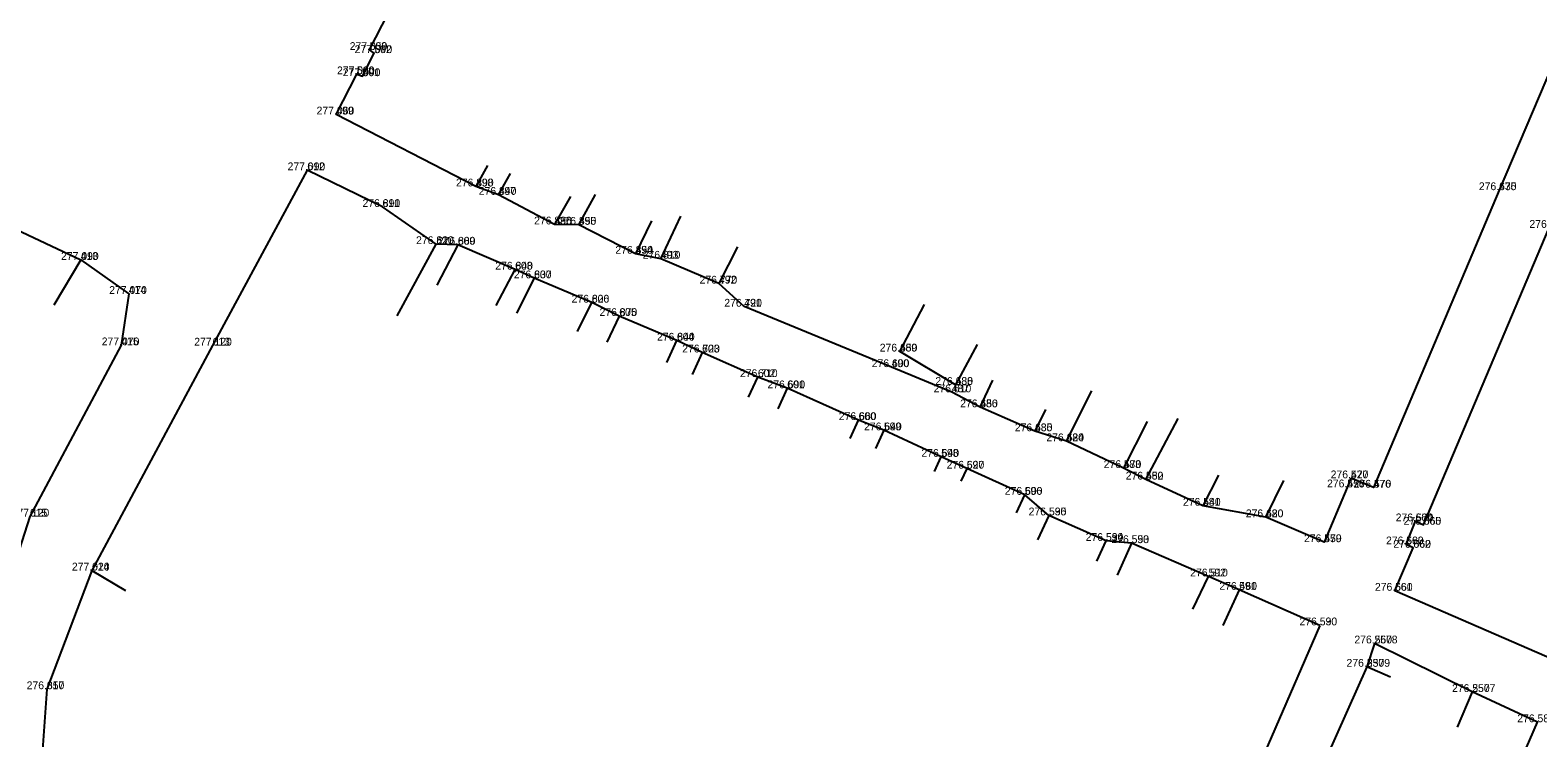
# Model space of a CAD drawing. Extents: x -776701 to -776081, y -974398 to -973771.
# Drawn here: x -776485.83 to -776437.45, y -974103.58 to -974080.86 of the extents above; entities that cross this region are included whole.
import ezdxf

# ---------------------------------------------------------------- set-up
doc = ezdxf.new("R2010")
doc.units = 0
for name, color, linetype in [('1 Body-bod', 7, 'Continuous'), ('11 Rozhrani-nezpev zpev schody', 7, 'Continuous'), ('2 Body-cislo', 7, 'Continuous'), ('3 Body-vyska', 7, 'Continuous'), ('47 Opěrné zdi', 7, 'Continuous'), ('7 Ploty', 7, 'Continuous')]:
    doc.layers.add(name, color=color, linetype=linetype)

msp = doc.modelspace()

# ---------------------------------------------------------------- linework, layer by layer
at = {"layer": '1 Body-bod'}
for p, q in [((-776474.94, -974081.5), (-776474.94, -974081.5)), ((-776474.79, -974081.6), (-776474.79, -974081.6)), ((-776475.35, -974082.28), (-776475.35, -974082.28)), ((-776475.17, -974082.34), (-776475.17, -974082.34)), ((-776476.01, -974083.57), (-776476.01, -974083.57)), ((-776476.94, -974085.36), (-776476.94, -974085.36)), ((-776471.53, -974085.88), (-776471.53, -974085.88)), ((-776470.8, -974086.15), (-776470.8, -974086.15)), ((-776438.7, -974086), (-776438.7, -974086)), ((-776474.53, -974086.54), (-776474.53, -974086.54)), ((-776469.01, -974087.1), (-776469.01, -974087.1)), ((-776468.23, -974087.11), (-776468.23, -974087.11)), ((-776472.8, -974087.73), (-776472.8, -974087.73)), ((-776472.11, -974087.75), (-776472.11, -974087.75)), ((-776466.41, -974088.04), (-776466.41, -974088.04)), ((-776465.59, -974088.2), (-776465.59, -974088.2)), ((-776484.21, -974088.24), (-776484.21, -974088.24)), ((-776470.27, -974088.55), (-776470.27, -974088.55)), ((-776469.66, -974088.83), (-776469.66, -974088.83)), ((-776463.73, -974089), (-776463.73, -974089)), ((-776482.67, -974089.33), (-776482.67, -974089.33)), ((-776467.81, -974089.61), (-776467.81, -974089.61)), ((-776466.93, -974090.04), (-776466.93, -974090.04)), ((-776462.92, -974089.74), (-776462.92, -974089.74)), ((-776482.91, -974090.98), (-776482.91, -974090.98)), ((-776479.98, -974090.99), (-776479.98, -974090.99)), ((-776465.08, -974090.83), (-776465.08, -974090.83)), ((-776464.27, -974091.21), (-776464.27, -974091.21)), ((-776457.93, -974091.18), (-776457.93, -974091.18)), ((-776462.48, -974092), (-776462.48, -974092)), ((-776458.19, -974091.68), (-776458.19, -974091.68)), ((-776461.54, -974092.36), (-776461.54, -974092.36)), ((-776456.26, -974092.49), (-776456.26, -974092.49)), ((-776456.14, -974092.25), (-776456.14, -974092.25)), ((-776455.35, -974092.97), (-776455.35, -974092.97)), ((-776459.25, -974093.38), (-776459.25, -974093.38)), ((-776458.44, -974093.71), (-776458.44, -974093.71)), ((-776453.59, -974093.74), (-776453.59, -974093.74)), ((-776452.58, -974094.06), (-776452.58, -974094.06)), ((-776456.6, -974094.56), (-776456.6, -974094.56)), ((-776455.78, -974094.94), (-776455.78, -974094.94)), ((-776450.75, -974094.92), (-776450.75, -974094.92)), ((-776450.03, -974095.29), (-776450.03, -974095.29)), ((-776443.45, -974095.25), (-776443.45, -974095.25)), ((-776453.92, -974095.78), (-776453.92, -974095.78)), ((-776443.57, -974095.54), (-776443.57, -974095.54)), ((-776442.73, -974095.55), (-776442.73, -974095.55)), ((-776453.14, -974096.44), (-776453.14, -974096.44)), ((-776448.2, -974096.13), (-776448.2, -974096.13)), ((-776446.18, -974096.5), (-776446.18, -974096.5)), ((-776441.38, -974096.63), (-776441.38, -974096.63)), ((-776441.12, -974096.74), (-776441.12, -974096.74)), ((-776451.31, -974097.26), (-776451.31, -974097.26)), ((-776450.49, -974097.33), (-776450.49, -974097.33)), ((-776444.31, -974097.3), (-776444.31, -974097.3)), ((-776441.68, -974097.37), (-776441.68, -974097.37)), ((-776441.45, -974097.48), (-776441.45, -974097.48)), ((-776483.85, -974098.21), (-776483.85, -974098.21)), ((-776448.02, -974098.4), (-776448.02, -974098.4)), ((-776447.04, -974098.83), (-776447.04, -974098.83)), ((-776442.04, -974098.86), (-776442.04, -974098.86)), ((-776444.45, -974099.97), (-776444.45, -974099.97)), ((-776442.7, -974100.55), (-776442.7, -974100.55)), ((-776442.94, -974101.3), (-776442.94, -974101.3)), ((-776485.3, -974102.02), (-776485.3, -974102.02)), ((-776439.56, -974102.11), (-776439.56, -974102.11)), ((-776437.47, -974103.08), (-776437.47, -974103.08))]:
    msp.add_line(p, q, dxfattribs=at)
at = {"layer": '11 Rozhrani-nezpev zpev schody'}
for points in [[(-776470.8, -974086.15), (-776471.53, -974085.88)], [(-776468.23, -974087.11), (-776469.01, -974087.1)], [(-776472.11, -974087.75), (-776472.8, -974087.73)], [(-776465.59, -974088.2), (-776466.41, -974088.04)], [(-776484.21, -974088.24), (-776482.67, -974089.33), (-776482.91, -974090.98), (-776485.84, -974096.48), (-776487.3, -974100.99), (-776488.57, -974104.39), (-776486.9, -974106.93), (-776485.66, -974109.13)], [(-776469.66, -974088.83), (-776470.27, -974088.55)], [(-776455.35, -974092.97), (-776456.26, -974092.49), (-776458.19, -974091.68), (-776462.92, -974089.74), (-776463.73, -974089)], [(-776466.93, -974090.04), (-776467.81, -974089.61)], [(-776464.27, -974091.21), (-776465.08, -974090.83)], [(-776461.54, -974092.36), (-776462.48, -974092)], [(-776458.44, -974093.71), (-776459.25, -974093.38)], [(-776452.58, -974094.06), (-776453.59, -974093.74)], [(-776455.78, -974094.94), (-776456.6, -974094.56)], [(-776450.03, -974095.29), (-776450.75, -974094.92)], [(-776443.45, -974095.25), (-776443.57, -974095.54)], [(-776453.14, -974096.44), (-776453.92, -974095.78)], [(-776446.18, -974096.5), (-776448.2, -974096.13)], [(-776450.49, -974097.33), (-776451.31, -974097.26)], [(-776483.85, -974098.21), (-776485.3, -974102.02), (-776485.51, -974105.02), (-776485.21, -974106.38), (-776483.71, -974108.28)], [(-776447.04, -974098.83), (-776448.02, -974098.4)], [(-776439.56, -974102.11), (-776442.7, -974100.55), (-776442.94, -974101.3)]]:
    msp.add_lwpolyline(points, dxfattribs=at)
at = {"layer": '47 Opěrné zdi'}
msp.add_lwpolyline([(-776489.898, -974087.219), (-776489.14, -974085.92), (-776484.21, -974088.24), (-776485.069, -974089.697)], dxfattribs=at)
at = {"layer": '7 Ploty'}
msp.add_line((-776439.56, -974102.11), (-776440.039, -974103.238), dxfattribs=at)
for points in [[(-776471.158, -974085.21), (-776471.53, -974085.88), (-776476.01, -974083.57), (-776475.35, -974082.28), (-776475.17, -974082.34), (-776474.79, -974081.6), (-776474.94, -974081.5), (-776473.93, -974079.51), (-776473.73, -974079.56), (-776473.34, -974078.78), (-776473.49, -974078.69), (-776470.85, -974073.57), (-776467.79, -974067.87), (-776466.73, -974065.16), (-776465.91, -974063.7), (-776465.72, -974063.74)], [(-776435.955, -974071.605), (-776435.57, -974070.85), (-776432.71, -974071.98), (-776434.19, -974075.53), (-776435.73, -974079.02), (-776438.7, -974086), (-776442.73, -974095.55), (-776443.45, -974095.25)], [(-776436.67, -974101.19), (-776442.04, -974098.86), (-776441.45, -974097.48), (-776441.68, -974097.37), (-776441.38, -974096.63), (-776441.12, -974096.74), (-776437.09, -974087.21), (-776434.16, -974080.3), (-776433.35, -974078.55), (-776432.69, -974076.73), (-776431.08, -974073.12)], [(-776474.057, -974090.034), (-776472.8, -974087.73), (-776474.53, -974086.54), (-776476.94, -974085.36), (-776479.98, -974090.99), (-776483.85, -974098.21), (-776482.77, -974098.857)], [(-776468.492, -974086.205), (-776469.01, -974087.1), (-776470.8, -974086.15), (-776470.42, -974085.46)], [(-776465.895, -974086.989), (-776466.41, -974088.04), (-776468.23, -974087.11), (-776467.69, -974086.143)], [(-776463.135, -974087.824), (-776463.73, -974089), (-776465.59, -974088.2), (-776464.956, -974086.836)], [(-776470.88, -974089.698), (-776470.27, -974088.55), (-776472.11, -974087.75), (-776472.785, -974089.047)], [(-776468.266, -974090.539), (-776467.81, -974089.61), (-776469.66, -974088.83), (-776470.228, -974089.947)], [(-776455.444, -974090.951), (-776456.14, -974092.25), (-776457.93, -974091.18), (-776457.14, -974089.671)], [(-776465.403, -974091.534), (-776465.08, -974090.83), (-776466.93, -974090.04), (-776467.325, -974090.879)], [(-776462.778, -974092.642), (-776462.48, -974092), (-776464.27, -974091.21), (-776464.589, -974091.913)], [(-776453.247, -974093.04), (-776453.59, -974093.74), (-776455.35, -974092.97), (-776454.945, -974092.101)], [(-776459.521, -974093.975), (-776459.25, -974093.38), (-776461.54, -974092.36), (-776461.838, -974093.021)], [(-776449.986, -974093.431), (-776450.75, -974094.92), (-776452.58, -974094.06), (-776451.767, -974092.44)], [(-776447.699, -974095.15), (-776448.2, -974096.13), (-776450.03, -974095.29), (-776448.993, -974093.328)], [(-776456.815, -974095.034), (-776456.6, -974094.56), (-776458.44, -974093.71), (-776458.705, -974094.295)], [(-776454.18, -974096.359), (-776453.92, -974095.78), (-776455.78, -974094.94), (-776455.968, -974095.346)], [(-776443.57, -974095.54), (-776444.31, -974097.3), (-776446.18, -974096.5), (-776445.608, -974095.316)], [(-776451.607, -974097.905), (-776451.31, -974097.26), (-776453.14, -974096.44), (-776453.507, -974097.229)], [(-776448.521, -974099.455), (-776448.02, -974098.4), (-776450.49, -974097.33), (-776450.956, -974098.355)], [(-776444.45, -974099.97), (-776447.04, -974098.83), (-776447.563, -974099.97)], [(-776444.45, -974099.97), (-776447.55, -974107.12)], [(-776442.181, -974101.633), (-776442.94, -974101.3), (-776444.22, -974104.18), (-776447.19, -974111.24), (-776447.3, -974111.21), (-776448.95, -974114.69), (-776448.81, -974114.76), (-776451.73, -974121.79), (-776451.81, -974121.76), (-776454.79, -974129.02), (-776457.78, -974135.74), (-776459.29, -974139.32)], [(-776443.232, -974113.037), (-776441.94, -974113.58), (-776440.43, -974110.04), (-776438.83, -974106.24), (-776437.47, -974103.08), (-776439.56, -974102.11)]]:
    msp.add_lwpolyline(points, dxfattribs=at)

# ---------------------------------------------------------------- texts
at = {"layer": '2 Body-cislo'}
for s, p in [('503', (-776474.94, -974081.5)), ('502', (-776474.79, -974081.6)), ('500', (-776475.35, -974082.28)), ('501', (-776475.17, -974082.34)), ('499', (-776476.01, -974083.57)), ('612', (-776476.94, -974085.36)), ('498', (-776471.53, -974085.88)), ('475', (-776438.7, -974086)), ('611', (-776474.53, -974086.54)), ('497', (-776470.8, -974086.15)), ('496', (-776469.01, -974087.1)), ('495', (-776468.23, -974087.11)), ('610', (-776472.8, -974087.73)), ('609', (-776472.11, -974087.75)), ('413', (-776484.21, -974088.24)), ('494', (-776466.41, -974088.04)), ('493', (-776465.59, -974088.2)), ('608', (-776470.27, -974088.55)), ('607', (-776469.66, -974088.83)), ('414', (-776482.67, -974089.33)), ('492', (-776463.73, -974089)), ('606', (-776467.81, -974089.61)), ('491', (-776462.92, -974089.74)), ('605', (-776466.93, -974090.04)), ('604', (-776465.08, -974090.83)), ('415', (-776482.91, -974090.98)), ('613', (-776479.98, -974090.99)), ('603', (-776464.27, -974091.21)), ('489', (-776457.93, -974091.18)), ('490', (-776458.19, -974091.68)), ('602', (-776462.48, -974092)), ('488', (-776456.14, -974092.25)), ('601', (-776461.54, -974092.36)), ('487', (-776456.26, -974092.49)), ('486', (-776455.35, -974092.97)), ('600', (-776459.25, -974093.38)), ('599', (-776458.44, -974093.71)), ('485', (-776453.59, -974093.74)), ('484', (-776452.58, -974094.06)), ('598', (-776456.6, -974094.56)), ('597', (-776455.78, -974094.94)), ('483', (-776450.75, -974094.92)), ('477', (-776443.45, -974095.25)), ('482', (-776450.03, -974095.29)), ('478', (-776443.57, -974095.54)), ('476', (-776442.73, -974095.55)), ('596', (-776453.92, -974095.78)), ('481', (-776448.2, -974096.13)), ('615', (-776485.84, -974096.48)), ('595', (-776453.14, -974096.44)), ('480', (-776446.18, -974096.5)), ('664', (-776441.38, -974096.63)), ('665', (-776441.12, -974096.74)), ('594', (-776451.31, -974097.26)), ('593', (-776450.49, -974097.33)), ('479', (-776444.31, -974097.3)), ('663', (-776441.68, -974097.37)), ('662', (-776441.45, -974097.48)), ('614', (-776483.85, -974098.21)), ('592', (-776448.02, -974098.4)), ('591', (-776447.04, -974098.83)), ('661', (-776442.04, -974098.86)), ('590', (-776444.45, -974099.97)), ('2578', (-776442.7, -974100.55)), ('2579', (-776442.94, -974101.3)), ('617', (-776485.3, -974102.02)), ('2577', (-776439.56, -974102.11))]:
    msp.add_text(s, height=0.25, dxfattribs=at).set_placement(p)
at = {"layer": '3 Body-vyska'}
for s, p in [('277.050', (-776475.579, -974081.5)), ('277.040', (-776475.422, -974081.6)), ('277.080', (-776475.986, -974082.28)), ('277.090', (-776475.802, -974082.34)), ('277.060', (-776476.642, -974083.57)), ('277.090', (-776477.572, -974085.36)), ('276.890', (-776472.168, -974085.88)), ('276.630', (-776439.347, -974086)), ('276.890', (-776475.168, -974086.54)), ('276.840', (-776471.438, -974086.15)), ('276.830', (-776469.661, -974087.1)), ('276.850', (-776468.875, -974087.11)), ('276.660', (-776437.724, -974087.21)), ('276.820', (-776473.449, -974087.73)), ('276.880', (-776472.752, -974087.75)), ('277.090', (-776484.842, -974088.24)), ('276.850', (-776467.055, -974088.04)), ('276.810', (-776466.177, -974088.2)), ('276.840', (-776470.908, -974088.55)), ('276.830', (-776470.311, -974088.83)), ('277.070', (-776483.296, -974089.33)), ('276.770', (-776464.352, -974089)), ('276.820', (-776468.459, -974089.61)), ('276.720', (-776463.559, -974089.74)), ('276.870', (-776467.562, -974090.04)), ('276.840', (-776465.718, -974090.83)), ('277.070', (-776483.536, -974090.98)), ('277.120', (-776480.568, -974090.99)), ('276.720', (-776464.909, -974091.21)), ('276.650', (-776458.571, -974091.18)), ('276.600', (-776458.828, -974091.68)), ('276.710', (-776463.057, -974092)), ('276.630', (-776456.787, -974092.25)), ('276.690', (-776462.174, -974092.36)), ('276.610', (-776456.843, -974092.49)), ('276.650', (-776455.991, -974092.97)), ('276.660', (-776459.884, -974093.38)), ('276.640', (-776459.074, -974093.71)), ('276.630', (-776454.237, -974093.74)), ('276.620', (-776453.225, -974094.06)), ('276.640', (-776457.234, -974094.56)), ('276.620', (-776456.425, -974094.94)), ('276.570', (-776451.385, -974094.92)), ('276.520', (-776444.102, -974095.25)), ('276.550', (-776450.678, -974095.29)), ('276.550', (-776444.218, -974095.54)), ('276.570', (-776443.365, -974095.55)), ('276.600', (-776454.558, -974095.78)), ('276.540', (-776448.841, -974096.13)), ('277.120', (-776486.428, -974096.48)), ('276.530', (-776453.793, -974096.44)), ('276.620', (-776446.825, -974096.5)), ('276.570', (-776442.015, -974096.63)), ('276.560', (-776441.761, -974096.74)), ('276.530', (-776451.963, -974097.26)), ('276.550', (-776451.138, -974097.33)), ('276.550', (-776444.958, -974097.3)), ('276.580', (-776442.325, -974097.37)), ('276.560', (-776442.091, -974097.48)), ('277.020', (-776484.493, -974098.21)), ('276.510', (-776448.609, -974098.4)), ('276.460', (-776447.674, -974098.83)), ('276.560', (-776442.681, -974098.86)), ('276.530', (-776445.103, -974099.97)), ('276.560', (-776443.341, -974100.55)), ('276.530', (-776443.593, -974101.3)), ('276.850', (-776485.945, -974102.02)), ('276.550', (-776440.208, -974102.11)), ('276.580', (-776438.115, -974103.08))]:
    msp.add_text(s, height=0.25, dxfattribs=at).set_placement(p)

doc.saveas('drawing.dxf')
